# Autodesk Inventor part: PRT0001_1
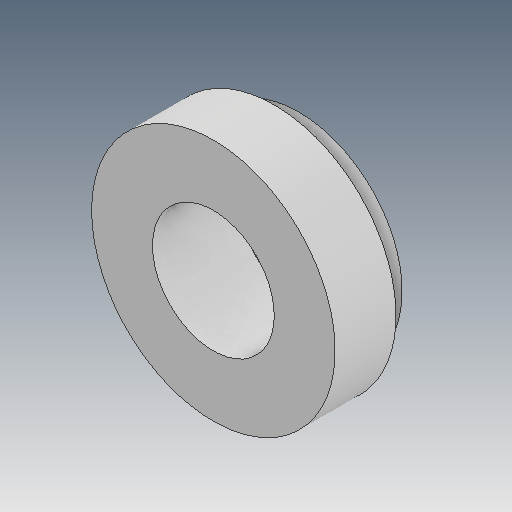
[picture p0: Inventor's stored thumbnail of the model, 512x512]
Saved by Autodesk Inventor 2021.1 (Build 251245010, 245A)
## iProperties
Created: 2019-04
Part Number: PRT0001_1
Material: Ogólny
Document SubType Name: Modeling
Designer: user
Density: 1 g/cm^3
Appearance: Domyślna
Author: user
Revision Number: ÈÎºÎ
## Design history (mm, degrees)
feature "ÊäÈë1"
node "Bryła1"
